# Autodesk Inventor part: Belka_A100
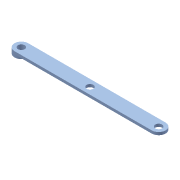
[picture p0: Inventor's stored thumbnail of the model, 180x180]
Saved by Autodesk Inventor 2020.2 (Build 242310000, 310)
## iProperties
Created: 2006-06
Part Number: Belka_A100
Document SubType Name: Modeling
Designer: F.Stasiak
Density: 1 g/cm^3
Material: Ogólny
Appearance: Niebieski pastelowy
Mass: 2157.08 g
Surface Area: 2690.6 cm^2
Volume: 2157.08 cm^3
Catalog Web Link: www.expertbooks.pl
Manager: www.cadconsulting.pl
Company: Fabian Stasiak CAD Consulting
Author: F.Stasiak
Subject: Zbiór ćwiczeń. Autodesk Inventor 2020. Kurs Professional
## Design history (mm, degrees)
sketch "Szkic1"
  geometry: L1 (0, 50)-(1000, 50); L2 (1000, -50)-(0, -50); L3 (0, 0)-(1000, 0); C1 r 25 at (0, 0); C2 r 25 at (1000, 0); C3 r 25 at (500, 0); A1 r 50 centre (1000, 0) between (1000, -50) and (1000, 50); A2 r 50 centre (0, 0) between (0, 50) and (0, -50); 1 further point
  constraints: 6 end point, 5 centre point, 4 point on circle, 4 tangent, 3 coincident, 2 equal radius, 2 parallel, 1 horizontal, 1 midpoint
  dimensions: "d0" = 50 radius of A2; "d1" = 1000 distance of L2.start L2.end; "d2" = 50 diameter of C1 (= d0)
extrude "Wyciągnięcie proste1" new body sketch "Szkic1" stored distance "d3" = 20; taper "d4" = 0 deg
sketch "Szkic2"
  geometry: C1 r 25 at (0, 0) reference; A1 r 50 centre (0, 0) between (0, -50) and (0, 50) reference; 2 further points
  constraints: 1 coincident, 1 vertical alignment, 2 other
extrude "Wyciągnięcie proste2" join sketch "Szkic2" distance "d5" = 20; taper "d6" = 0 deg
node "Bryła1"
node "Korpusy bryłowe"
node "Korpusy powierzchniowe"
